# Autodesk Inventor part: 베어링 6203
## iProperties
IsCustomPart: 0
Created: 2014-10
Part Number: 베어링 6203
Material: Steel, Mild
Description: 깊은 그루브 볼 베어링
Document SubType Name: Modeling
Standard: KS B 2023
Designer: KYOUNG IL JANG
Standards Organization: KS
Language: ko-KR
Size Designation: 6203 - 17 x 40 x 12
Categories: <MemberInstance><Categories><Category DisplayName="샤프트 부품" InternalName="7f7aeb1f-a693-4053-b835-cee3144e0d98" Mnemonic="SHFT"><Category DisplayName="베어링" Inter
Density: 7.86 g/cm^3
Mass: 64.9809 g
Surface Area: 64.3582 cm^2
Volume: 8.26729 cm^3
Author: SeoGD™ [www.esajin.kr]
Revision Number: 1
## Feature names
1. IDS_ARRAYBALL[SIMPL:T] [Circular Pattern]
